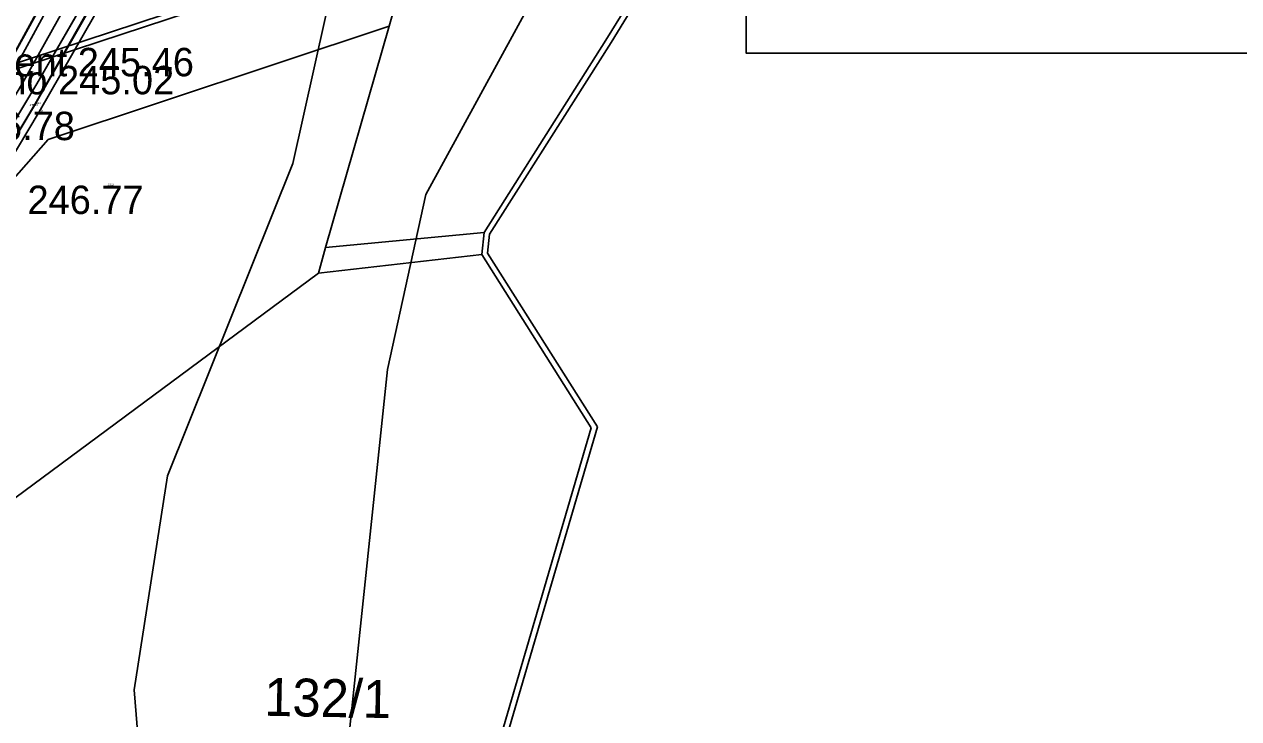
# Model space of a CAD drawing. Extents: x -555757 to -553364, y -1100723 to -1096439.
# Drawn here: x -554242.8 to -554178.6, y -1096911.4 to -1096874.8 of the extents above; entities that cross this region are included whole.
import ezdxf

# ---------------------------------------------------------------- set-up
doc = ezdxf.new("R2010")
doc.units = 0
for name, color, linetype in [('00_NÁVRH - 0.18 mm', 7, 'Continuous'), ('00_NÁVRH - 0.35 mm', 7, 'Continuous'), ('00_NÁVRH - Popis', 7, 'Continuous'), ('01_HLADINA', 7, 'Continuous'), ('C$SLO$PARCELY', 7, 'Continuous'), ('Geodet. výšky - netisknuté', 7, 'Continuous'), ('HRANA$SVAHU', 7, 'Continuous'), ('HRANICE$PARCELY', 7, 'Continuous'), ('OSA$KOLEJI', 7, 'Continuous'), ('POPIS', 7, 'Continuous'), ('ROZHRANI', 7, 'Continuous'), ('SLUCKOV$$C$RA', 7, 'Continuous'), ('VYSKA_PODR_BOD', 7, 'Continuous'), ('zájem', 7, 'Continuous')]:
    doc.layers.add(name, color=color, linetype=linetype)

# ---------------------------------------------------------------- blocks, each defined once
blk = doc.blocks.new('POINT_DISPLAY')
blk.add_line((0, 0), (0, 0))

msp = doc.modelspace()

# ---------------------------------------------------------------- linework, layer by layer
at = {"layer": '00_NÁVRH - 0.18 mm'}
for points in [[(-554244.222, -1096877.946), (-554239.928, -1096870.081), (-554234.389, -1096860.12), (-554233.805, -1096859.133), (-554230.381, -1096853.989), (-554224.046, -1096843.91), (-554222.437, -1096841.751), (-554216.84, -1096834.596), (-554215.638, -1096833.106), (-554214.628, -1096832.253), (-554213.878, -1096831.54), (-554208.044, -1096827.257), (-554206.604, -1096826.656), (-554199.585, -1096824.093), (-554195.86, -1096822.69), (-554194.845, -1096822.577), (-554193.89, -1096822.47)], [(-554257.674, -1096913.609), (-554257.386, -1096904.184), (-554257.334, -1096903.927), (-554257.244, -1096903.68), (-554253.91, -1096896.5), (-554246.263, -1096883.55), (-554242.882, -1096877.885), (-554232.814, -1096859.873), (-554221.954, -1096844.276), (-554214.583, -1096834.434), (-554207.357, -1096828.39), (-554204.597, -1096827.342), (-554200.893, -1096825.981), (-554199.43, -1096825.685), (-554196.267, -1096825.045), (-554193.7, -1096825.229), (-554189.701, -1096825.925)], [(-554256.602, -1096912.935), (-554256.472, -1096905.789), (-554256.409, -1096904.621), (-554256.316, -1096904.033), (-554256.192, -1096903.62), (-554254.599, -1096900.381), (-554252.831, -1096896.798), (-554252.356, -1096895.943), (-554242.247, -1096879.075), (-554238.131, -1096871.857), (-554232.321, -1096861.512), (-554230.576, -1096858.893), (-554220.275, -1096844.692), (-554215.749, -1096838.882), (-554212.975, -1096835.911), (-554211.13, -1096834.122), (-554207.196, -1096830.262), (-554206.098, -1096829.593), (-554204.263, -1096829.043), (-554200.835, -1096828.054), (-554199.681, -1096827.841), (-554198.092, -1096827.737), (-554194.79, -1096827.55)]]:
    msp.add_lwpolyline(points, dxfattribs=at)
at = {"layer": '00_NÁVRH - 0.35 mm'}
for points in [[(-554258.424, -1096913.609), (-554258.136, -1096904.184), (-554258.084, -1096903.927), (-554257.994, -1096903.657), (-554254.805, -1096896.5), (-554254.006, -1096895.143), (-554247.013, -1096883.55), (-554243.71, -1096877.885), (-554234.133, -1096860.293), (-554233.564, -1096859.274), (-554223.04, -1096843.11), (-554215.394, -1096833.291), (-554213.531, -1096831.866), (-554207.751, -1096827.646), (-554205.603, -1096826.85), (-554202.523, -1096825.678), (-554200.576, -1096824.944), (-554197.017, -1096823.505), (-554194.826, -1096822.911)], [(-554256.924, -1096913.609), (-554256.636, -1096904.184), (-554256.584, -1096903.927), (-554256.474, -1096903.627), (-554253.291, -1096896.909), (-554252.611, -1096895.819), (-554245.513, -1096883.55), (-554242.132, -1096877.928), (-554232.557, -1096861.353), (-554231.794, -1096860.142), (-554228.306, -1096855.295), (-554220.288, -1096844.276), (-554213.58, -1096835.32), (-554211.681, -1096833.605), (-554206.88, -1096829.27), (-554200.66, -1096827.458), (-554198.89, -1096827.18)]]:
    msp.add_lwpolyline(points, dxfattribs=at)
at = {"layer": '00_NÁVRH - Popis'}
msp.add_lwpolyline([(-554204.667, -1096866.109), (-554156.972, -1096866.109), (-554156.972, -1096876.306), (-554204.667, -1096876.306)], close=True, dxfattribs=at)
at = {"layer": '01_HLADINA'}
for p, q in [((-554197.513, -1096839.721), (-554221.584, -1096883.775)), ((-554235.18, -1096862.215), (-554243.71, -1096877.885)), ((-554242.132, -1096877.928), (-554232.786, -1096861.75)), ((-554245.513, -1096883.55), (-554242.132, -1096877.928)), ((-554221.584, -1096883.775), (-554223.598, -1096893.011)), ((-554223.598, -1096893.011), (-554227.357, -1096928.627))]:
    msp.add_line(p, q, dxfattribs=at)
at = {"layer": 'HRANA$SVAHU'}
for p, q in [((-554234.01, -1096859.43), (-554243.79, -1096877.22)), ((-554242.22, -1096878.99), (-554231.72, -1096860.45)), ((-554242, -1096879.4), (-554231.27, -1096860.66)), ((-554252.85, -1096896.77), (-554242.22, -1096878.99)), ((-554252.33, -1096896.62), (-554242, -1096879.4))]:
    msp.add_line(p, q, dxfattribs=at)
at = {"layer": 'HRANICE$PARCELY'}
for p, q in [((-554212.08, -1096875.63), (-554205.44, -1096864.88)), ((-554221.7, -1096868.36), (-554223.51, -1096874.88)), ((-554222.22, -1096870.23), (-554243.68, -1096877.3)), ((-554223.51, -1096874.88), (-554241.53, -1096880.86)), ((-554223.51, -1096874.88), (-554226.88, -1096886.57)), ((-554218.5, -1096885.77), (-554212.08, -1096875.63)), ((-554241.53, -1096880.86), (-554253.6, -1096894.54)), ((-554218.5, -1096885.77), (-554218.63, -1096886.93)), ((-554227.24, -1096887.92), (-554226.88, -1096886.57)), ((-554212.84, -1096896.08), (-554218.63, -1096886.93)), ((-554227.24, -1096887.92), (-554244.77, -1096900.89)), ((-554222.58, -1096929.24), (-554212.84, -1096896.08))]:
    msp.add_line(p, q, dxfattribs=at)
at = {"layer": 'POPIS'}
for p, q in [((-554211.796, -1096875.741), (-554205.165, -1096865.005)), ((-554222.465, -1096869.995), (-554243.849, -1096877.04)), ((-554218.21, -1096885.871), (-554211.796, -1096875.741)), ((-554218.21, -1096885.871), (-554218.32, -1096886.858)), ((-554212.514, -1096896.034), (-554218.32, -1096886.858)), ((-554222.28, -1096929.284), (-554212.514, -1096896.034))]:
    msp.add_line(p, q, dxfattribs=at)
at = {"layer": 'SLUCKOV$$C$RA'}
for p, q in [((-554226.88, -1096886.57), (-554218.5, -1096885.77)), ((-554218.63, -1096886.93), (-554227.24, -1096887.92))]:
    msp.add_line(p, q, dxfattribs=at)
at = {"layer": 'zájem'}
for points in [[(-554190.63, -1097034.96), (-554197.16, -1097028.05), (-554217.46, -1096987.98), (-554225.33, -1096977.64), (-554234.21, -1096944.26), (-554236.99, -1096909.92), (-554235.22, -1096898.62), (-554228.6, -1096882.13), (-554225.73, -1096869.26), (-554224.9, -1096864.61), (-554233.29, -1096868.06), (-554243.42, -1096872.22), (-554247.48, -1096879.5), (-554255.66, -1096892.57), (-554260.45, -1096913.44), (-554248.68, -1096931.61), (-554247, -1096951.09), (-554248.74, -1096969.23), (-554247.82, -1097012.49), (-554234.69, -1097042.48)], [(-554234.69, -1097042.48), (-554247.82, -1097012.49), (-554248.74, -1096969.23), (-554247, -1096951.09), (-554248.68, -1096931.61), (-554260.45, -1096913.44), (-554255.66, -1096892.57), (-554247.48, -1096879.5), (-554243.42, -1096872.22), (-554233.29, -1096868.06), (-554224.9, -1096864.61), (-554225.73, -1096869.26), (-554228.6, -1096882.13), (-554235.22, -1096898.62), (-554236.99, -1096909.92), (-554234.21, -1096944.26), (-554225.33, -1096977.64), (-554217.46, -1096987.98), (-554197.16, -1097028.05), (-554190.63, -1097034.96)]]:
    msp.add_lwpolyline(points, dxfattribs=at)

# ---------------------------------------------------------------- block references
at = {"layer": 'ROZHRANI'}
for p in [(-554242.22, -1096878.99), (-554242, -1096879.4), (-554238.37, -1096883.3)]:
    msp.add_blockref('POINT_DISPLAY', p, dxfattribs=at)

# ---------------------------------------------------------------- texts
at = {"layer": 'C$SLO$PARCELY'}
msp.add_text('132/1', height=2, rotation=358.90286, dxfattribs=at).set_placement((-554230.127, -1096911.284))
at = {"layer": 'Geodet. výšky - netisknuté'}
msp.add_text('245.93', height=0.1, dxfattribs=at).set_placement((-554242.503, -1096879.09))
at = {"layer": 'OSA$KOLEJI'}
for s, p in [('2310', (-554242.22, -1096878.99)), ('2311', (-554242, -1096879.4)), ('2312', (-554238.37, -1096883.3))]:
    msp.add_text(s, height=0.1, dxfattribs=at).set_placement(p)
at = {"layer": 'POPIS'}
for s, p in [('sediment 245.46', (-554248.66, -1096877.529)), ('dno 245.02', (-554244.91, -1096878.479))]:
    msp.add_text(s, height=1.5, dxfattribs=at).set_placement(p)
at = {"layer": 'VYSKA_PODR_BOD'}
for s, p in [('246.78', (-554246.25, -1096880.9)), ('246.77', (-554242.62, -1096884.8))]:
    msp.add_text(s, height=1.5, dxfattribs=at).set_placement(p)

doc.saveas('drawing.dxf')
